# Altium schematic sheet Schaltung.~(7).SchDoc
size A4
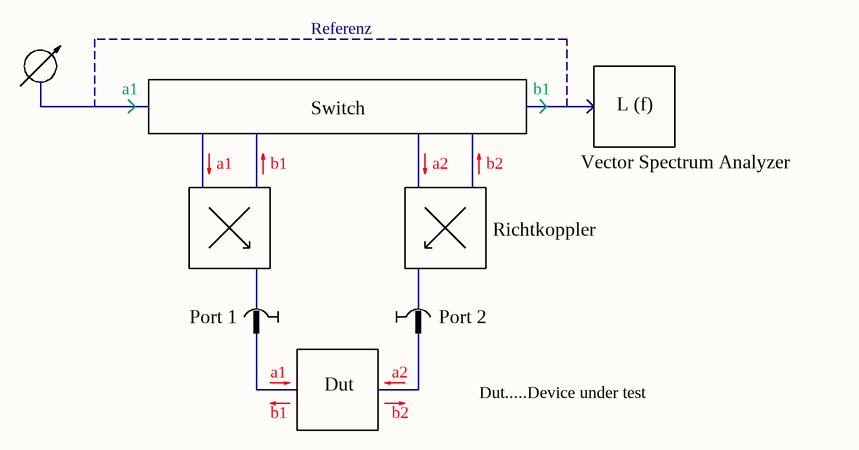
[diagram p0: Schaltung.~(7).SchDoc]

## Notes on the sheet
- Referenz
- a1
- Switch
- b1
- L (f)
- a2
- b2
- Vector Spectrum Analyzer
- Richtkoppler
- Port 1
- Port 2
- Dut
- Dut.....Device under test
